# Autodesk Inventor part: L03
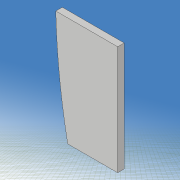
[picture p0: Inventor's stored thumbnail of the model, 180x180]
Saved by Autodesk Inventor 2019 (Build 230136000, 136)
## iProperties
Created: 2021-05
Part Number: L03
Material: 一般
Document SubType Name: Modeling
Designer: kikut
Density: 1 g/cm^3
Appearance: 既定
Mass: 0.00934248 g
Surface Area: 0.426451 cm^2
Volume: 0.00934248 cm^3
Author: kikut
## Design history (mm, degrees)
sketch "スケッチ1"
  geometry: L1 (80, 60)-(-80, 60); L2 (-80, 60)-(-80, -60); L3 (-80, -60)-(80, -60); L4 (80, -60)-(80, 60); L5 (80, 60)-(-80, -60); L6 (-80, 60)-(80, -60); 1 further point
  constraints: 12 end point, 2 midpoint, 2 parallel, 1 horizontal, 1 perpendicular
  dimensions: "d0" = 160 distance of L2.end L3.end; "d1" = 120 distance of L1.end L2.end
extrude "押し出し1" new body sketch "スケッチ1" stored distance "d2" = 0.6; taper "d3" = 0 deg
sketch "スケッチ2"
  geometry: L1 (-140, 0)-(140, 0) reference; L2 (0, -54)-(20, -30); L3 (0, 54)-(20, 30); L4 (0, -3)-(6.514, -3); L5 (6.514, -3)-(16, -6); L6 (16, -6)-(24, -3); L7 (24, -3)-(33.716, -3); L8 (0, 3)-(6.514, 3); L9 (6.514, 3)-(16, 6); L10 (16, 6)-(24, 3); L11 (24, 3)-(33.716, 3); L12 (0, -98)-(0, 98) reference; L13 (-100, -70)-(100, -70); L14 (100, -70)-(100, 70); L15 (100, 70)-(-100, 70); L16 (-100, 70)-(-100, -70); L17 (-100, -70)-(100, 70); L18 (100, -70)-(-100, 70); A1 r 60 centre (54.312, 28.5) between (0, 54) and (0, 3); A2 r 60 centre (54.312, -28.5) between (0, -3) and (0, -54); A3 r 18.111 centre (18, -12) between (20, -30) and (33.716, -3); A4 r 18.111 centre (18, 12) between (33.716, 3) and (20, 30); 1 further point
  constraints: 32 end point, 8 point on circle, 8 symmetric about line, 4 centre point, 3 horizontal, 2 collinear, 2 midpoint, 2 parallel, 1 perpendicular
  dimensions: "d5" = 60 radius of A1; "d6" = 6 distance of L8.start L4.start; "d7" = 108 distance of L3.start L2.start; "d8" = 0 horizontal distance of L3.start L8.start; "d9" = 60 distance of L3.end L2.end; "d10" = 0 horizontal distance of point (0, 0) L3.start; "d11" = 20 horizontal distance of L3.start L3.end; "d12" = 24 distance of A4.centre A3.centre; "d13" = 6 distance of L11.end L7.end; "d14" = 12 distance of L9.end L5.end; "d15" = 16 distance from line of L12 L5.end; "d16" = 24 distance from line of L6.end L12; "d17" = 200 distance of L14.end L15.end; "d18" = 140 distance of L15.end L13.start; "d30" = 18 distance from line of L12 A4.centre
extrude "押し出し2" cut sketch "スケッチ2" stored distance "d19" = 10; taper "d20" = 0 deg
sketch "スケッチ3"
  geometry: L1 (49.705, -17.97)-(33.948, -15.191); L2 (33.948, -15.191)-(34.295, -13.222); L3 (34.295, -13.222)-(50.052, -16); L4 (50.052, -16)-(49.705, -17.97); L5 (49.705, -17.97)-(34.295, -13.222); L6 (33.948, -15.191)-(50.052, -16); L7 (50.052, 16)-(34.295, 13.222); L8 (34.295, 13.222)-(33.948, 15.191); L9 (33.948, 15.191)-(49.705, 17.97); L10 (49.705, 17.97)-(50.052, 16); L11 (50.052, 16)-(33.948, 15.191); L12 (34.295, 13.222)-(49.705, 17.97); L13 (-112, 0)-(112, 0) reference; L14 (0, -84)-(0, 84) reference; 3 further points
  constraints: 24 end point, 4 midpoint, 4 parallel, 2 perpendicular, 2 symmetric about line
  dimensions: "d21" = 2 distance of L3.end L1.start; "d22" = 2 distance of L9.end L7.start; "d23" = 16 distance of L8.end L9.end; "d24" = 42 distance from line of L14 point (42, 15.596); "d26" = 10 deg angle of L7 L13; "d62" = 16 distance from line of L3.end L13
extrude "押し出し3" join sketch "スケッチ3" distance "d27" = 0.6; taper "d28" = 0 deg
fillet "フィレット1" dims "d31" = 2
fillet "フィレット2" dims "d32" = 1
sketch "スケッチ7"
  geometry: L1 (-20, 60)-(80, 60); L2 (80, 60)-(80, -60); L3 (80, -60)-(-20, -60); L4 (-20, -60)-(-20, 60); L5 (0, -82.207)-(0, 85.793) reference; L6 (-40, 0)-(100, 0) reference; L7 (-10, -30)-(0, -30); L8 (0, -30)-(0, -40); L9 (0, -40)-(-10, -40); L10 (-10, -40)-(-10, -30); 1 further point
  constraints: 16 end point, 4 parallel, 2 horizontal, 2 perpendicular, 1 other
  dimensions: "d80" = 120 distance of L3.end L1.start; "d81" = 20 distance between parallel lines of L5 L4; "d82" = 100 distance of L1.start L1.end; "d84" = 10 distance of L8.end L9.end; "d85" = 10 distance of L7.end L8.end; "d86" = 10 distance between parallel lines of L4 L10; "d89" = 20 distance between parallel lines of L3 L9
extrude "押し出し5" cut sketch "スケッチ7" stored distance "d87" = 10; taper "d88" = 0 deg
node "ソリッド1"
